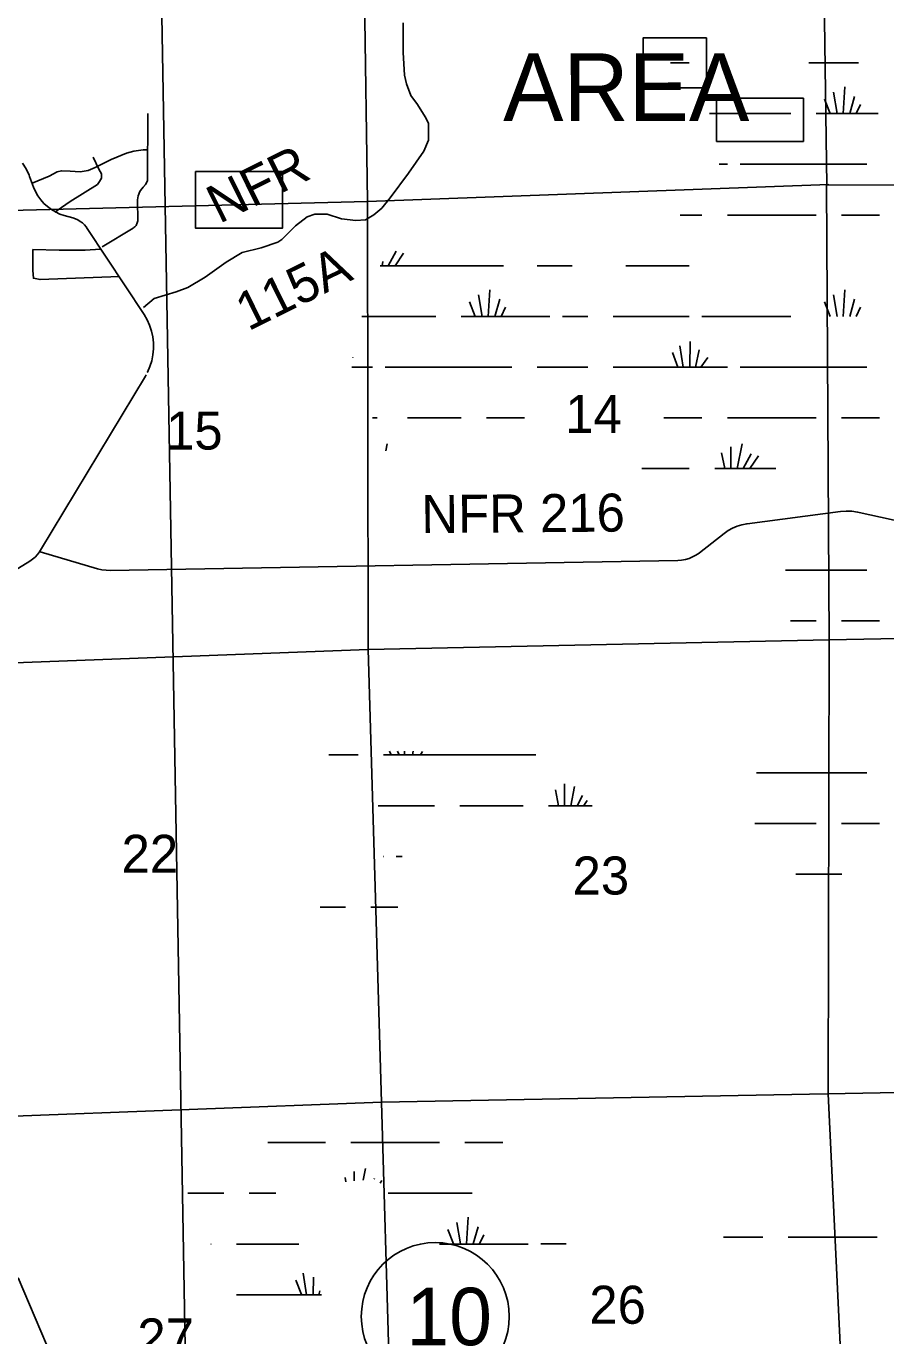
# Model space of a CAD drawing. Extents: x 2480962 to 2688785, y 277103 to 599240.
# Drawn here: x 2598432 to 2608603, y 442588 to 458082 of the extents above; entities that cross this region are included whole.
import ezdxf

# ---------------------------------------------------------------- set-up
doc = ezdxf.new("R2010")
doc.units = 0
for name, color, linetype in [('Divided_Highway', 7, 'Continuous'), ('Level 31', 7, 'Continuous'), ('Level 44', 7, 'Continuous'), ('Local Roads Improved', 7, 'Continuous'), ('Local Roads Related Text', 7, 'Continuous'), ('Planning Number US Highways', 7, 'Continuous'), ('Section Lines', 7, 'Continuous'), ('Section Numbers', 7, 'Continuous'), ('Swamps', 7, 'Continuous')]:
    doc.layers.add(name, color=color, linetype=linetype)

msp = doc.modelspace()

# ---------------------------------------------------------------- linework, layer by layer
at = {"layer": 'Divided_Highway'}
msp.add_line((2600799.421, 414762.355), (2600001.432, 460214.017), dxfattribs=at)
at = {"layer": 'Level 31'}
for points in [[(2606481.942, 457943.709), (2605731.294, 457943.709), (2605731.294, 457350.694), (2606481.942, 457350.694)], [(2607627.668, 457232.091), (2606600.465, 457232.091), (2606600.465, 456718.144), (2607627.668, 456718.144)], [(2601464.45, 456362.335), (2600437.247, 456362.335), (2600437.247, 455690.25), (2601464.45, 455690.25)]]:
    msp.add_lwpolyline(points, close=True, dxfattribs=at)
at = {"layer": 'Local Roads Improved'}
for p, q in [((2599873.012, 457047.638), (2599868.465, 456285.277)), ((2598471.682, 456302.805), (2598518.787, 456177.402)), ((2599830.334, 456192.694), (2599814.374, 456176.413)), ((2599749.023, 456013.245), (2599752.022, 455791.542)), ((2598880.665, 455843.218), (2598985.492, 455813.1)), ((2599154.919, 455688.573), (2599827.03, 454669.258)), ((2599697.771, 455693.41), (2599332.347, 455470.758)), ((2598602.645, 451882.083), (2599842.081, 453942.71)), ((2606964.152, 452195.687), (2608066.39, 452338.855)), ((2608289.097, 452329.141), (2611255.027, 451677.276)), ((2606399.373, 451853.027), (2606689.888, 452080.714)), ((2598599.058, 451861.375), (2599274.31, 451663.367)), ((2597005.743, 450854.193), (2598474.557, 451753.012)), ((2599425.601, 451643.007), (2606142.68, 451761.873)), ((2598672.824, 442484.922), (2598337.502, 443272.871))]:
    msp.add_line(p, q, dxfattribs=at)
for points in [[(2599818.162, 454754.215), (2599947.956, 454859.672), (2600207.544, 454940.794), (2600345.45, 454989.466), (2600548.254, 455111.148), (2600799.73, 455289.615), (2600986.309, 455403.185), (2601213.449, 455459.97), (2601408.14, 455524.867), (2601456.813, 455557.316), (2601619.056, 455719.559), (2601756.962, 455825.016), (2601846.195, 455857.465), (2601992.214, 455857.465), (2602162.569, 455800.68), (2602332.924, 455784.456), (2602446.493, 455792.568), (2602543.839, 455849.353), (2602641.185, 455930.474), (2602738.53, 456052.156), (2602957.558, 456344.193), (2603136.025, 456603.781), (2603192.81, 456733.576), (2603192.81, 456855.258), (2603192.81, 456936.379), (2603152.249, 457009.388), (2603063.016, 457155.407), (2602981.894, 457260.864), (2602933.222, 457398.771), (2602908.885, 457504.228), (2602892.661, 457771.929), (2602892.661, 458031.517), (2602892.661, 458120.751)], [(2598501.56, 456223.333), (2598704.41, 456308.31), (2598800.352, 456357.652), (2598849.694, 456371.358), (2598951.119, 456365.876), (2599071.733, 456360.394), (2599164.934, 456374.1), (2599249.912, 456409.735), (2599436.315, 456502.937), (2599619.976, 456579.691), (2599704.954, 456604.362), (2599814.603, 456618.068), (2599861.203, 456620.809), (2599861.203, 456620.809)], [(2598389.53, 456462.342), (2598431.13, 456392.844), (2598465.238, 456319.379), (2598471.682, 456302.805)], [(2599225.241, 456533.09), (2599291.03, 456390.547), (2599321.184, 456335.723), (2599321.184, 456283.639), (2599299.254, 456245.262), (2599274.583, 456209.627), (2598953.861, 456006.776), (2598800.352, 455902.61), (2598775.681, 455883.422)], [(2598518.787, 456177.402), (2598541.752, 456124.804), (2598570.09, 456074.896), (2598603.489, 456028.222), (2598641.585, 455985.295), (2598683.958, 455946.586), (2598730.146, 455912.517), (2598779.642, 455883.464), (2598831.904, 455859.744), (2598880.665, 455843.218)], [(2599814.374, 456176.413), (2599798.536, 456158.466), (2599784.662, 456138.964), (2599772.901, 456118.117), (2599763.384, 456096.155), (2599756.215, 456073.319), (2599751.472, 456049.859), (2599749.207, 456026.031), (2599749.023, 456013.245)], [(2599868.465, 456285.277), (2599867.651, 456271.338), (2599865.386, 456257.561), (2599861.691, 456244.096), (2599856.61, 456231.091), (2599850.197, 456218.688), (2599842.523, 456207.024), (2599833.672, 456196.226), (2599830.334, 456192.694)], [(2598985.492, 455813.1), (2599015.499, 455802.75), (2599044.26, 455789.319), (2599071.459, 455772.956), (2599096.799, 455753.84), (2599120.003, 455732.179), (2599140.815, 455708.212), (2599154.919, 455688.573)], [(2599752.022, 455791.542), (2599751.563, 455779.71), (2599749.869, 455767.991), (2599746.959, 455756.514), (2599742.866, 455745.404), (2599737.633, 455734.782), (2599731.319, 455724.764), (2599723.994, 455715.463), (2599715.735, 455706.978), (2599706.635, 455699.403), (2599697.771, 455693.41)], [(2599534.77, 455120.164), (2598595.903, 455083.652), (2598517.664, 455099.3), (2598512.448, 455193.187), (2598512.448, 455412.256), (2598512.448, 455438.336), (2598820.188, 455433.12), (2599127.928, 455433.12), (2599310.485, 455443.551)], [(2599827.03, 454669.258), (2599863.133, 454607.721), (2599892.607, 454542.747), (2599915.127, 454475.048), (2599930.447, 454405.366), (2599938.4, 454334.465), (2599938.898, 454263.119), (2599931.936, 454192.114), (2599917.59, 454122.224), (2599896.017, 454054.217), (2599867.454, 453988.838), (2599864.371, 453982.758)], [(2599842.081, 453942.71), (2599850.713, 453957.478)], [(2608066.39, 452338.855), (2608134.06, 452344.063), (2608201.904, 452342.169), (2608269.179, 452333.193), (2608289.097, 452329.141)], [(2606689.888, 452080.714), (2606738.021, 452114.526), (2606789.423, 452143.12), (2606843.534, 452166.186), (2606899.759, 452183.469), (2606957.483, 452194.78), (2606964.152, 452195.687)], [(2598474.557, 451753.012), (2598507.557, 451775.662), (2598538.008, 451801.637), (2598565.579, 451830.653), (2598589.964, 451862.392), (2598602.645, 451882.083)], [(2606142.68, 451761.873), (2606187.414, 451765.013), (2606231.574, 451772.81), (2606274.677, 451785.181), (2606316.251, 451801.99), (2606355.841, 451823.052), (2606393.012, 451848.137), (2606399.373, 451853.027)], [(2599274.31, 451663.367), (2599325.829, 451651.147), (2599378.344, 451644.38), (2599425.601, 451643.007)]]:
    msp.add_lwpolyline(points, dxfattribs=at)
at = {"layer": 'Planning Number US Highways'}
msp.add_circle((2603272.369, 442816.14), 875, dxfattribs=at)
at = {"layer": 'Section Lines'}
for p, q in [((2607834.885, 461478.013), (2607905.041, 456199.96)), ((2602470.87, 456008.717), (2602392.032, 461297.775)), ((2602470.87, 456008.768), (2607929.608, 456207.264)), ((2607903.429, 456206.309), (2613360.162, 456178.288)), ((2607903.429, 456206.309), (2607931.911, 450819.864)), ((2597223.549, 455875.68), (2602470.87, 456008.717)), ((2602478.304, 450708.223), (2602470.87, 456008.768)), ((2607931.911, 450819.864), (2613319.455, 450926.862)), ((2602478.304, 450708.223), (2607931.911, 450819.864)), ((2607931.911, 450819.864), (2607919.944, 445449.014)), ((2602478.306, 450708.223), (2597332.488, 450513.138)), ((2602636.608, 445353.54), (2602478.306, 450708.223)), ((2607912.122, 445448.861), (2613411.446, 445556.59)), ((2597403.462, 445151.69), (2602636.608, 445353.54)), ((2602636.608, 445353.54), (2607912.122, 445448.861)), ((2602790.466, 440010.561), (2602636.608, 445353.54)), ((2607919.944, 445449.014), (2608176.107, 440121.819))]:
    msp.add_line(p, q, dxfattribs=at)
at = {"layer": 'Swamps'}
for p, q in [((2607692.038, 457647.508), (2608278.299, 457647.516)), ((2608028.816, 457047.591), (2607982.56, 457301.974)), ((2608099.816, 457047.542), (2608117.051, 457363.618)), ((2608176.502, 457047.721), (2608234.734, 457251.542)), ((2607943.742, 457047.678), (2607878.268, 457219.545)), ((2608253.098, 457047.644), (2608301.982, 457156.277)), ((2607778.306, 457047.505), (2608511.996, 457047.515)), ((2606878.314, 456447.488), (2608378.316, 456447.509)), ((2606728.322, 455847.482), (2607778.324, 455847.497)), ((2608078.324, 455847.501), (2608528.325, 455847.507)), ((2602895.489, 455397.247), (2602796.17, 455248.265)), ((2604478.327, 455247.447), (2604890.594, 455247.453)), ((2605528.328, 455247.462), (2605978.329, 455247.468)), ((2605978.329, 455247.468), (2606278.33, 455247.472)), ((2603899.843, 454647.467), (2603917.079, 454963.543)), ((2608099.851, 454647.525), (2608117.086, 454963.602)), ((2603743.769, 454647.604), (2603678.295, 454819.47)), ((2603828.843, 454647.516), (2603782.587, 454901.899)), ((2603976.529, 454647.646), (2604034.761, 454851.467)), ((2604053.125, 454647.569), (2604102.009, 454756.203)), ((2607943.776, 454647.662), (2607878.303, 454819.528)), ((2608028.851, 454647.574), (2607982.595, 454901.957)), ((2608176.537, 454647.704), (2608234.769, 454851.526)), ((2608253.133, 454647.627), (2608302.017, 454756.261)), ((2603578.333, 454647.431), (2604628.335, 454647.445)), ((2604778.336, 454647.447), (2605078.336, 454647.451)), ((2605378.337, 454647.456), (2605978.338, 454647.464)), ((2605978.338, 454647.464), (2606278.338, 454647.468)), ((2606428.339, 454647.47), (2607478.341, 454647.485)), ((2606206.349, 454047.527), (2606166.954, 454300.763)), ((2606284.511, 454047.483), (2606290.238, 454351.199)), ((2606144.027, 454048.449), (2606077.955, 454221.244)), ((2606351.61, 454047.275), (2606394.494, 454253.128)), ((2606413.806, 454046.968), (2606497.584, 454160.67)), ((2602678.34, 454047.414), (2604178.343, 454047.435)), ((2604478.343, 454047.439), (2605078.345, 454047.448)), ((2605378.345, 454047.452), (2605978.346, 454047.46)), ((2605978.346, 454047.46), (2606728.348, 454047.47)), ((2606878.348, 454047.472), (2608378.351, 454047.493)), ((2602528.348, 453447.409), (2602586.57, 453447.409)), ((2602944.57, 453447.414), (2603578.35, 453447.423)), ((2603878.351, 453447.427), (2604328.352, 453447.433)), ((2605978.355, 453447.456), (2606428.356, 453447.462)), ((2606728.356, 453447.466), (2607778.358, 453447.481)), ((2608078.359, 453447.485), (2608528.36, 453447.491)), ((2606769.307, 453106.027), (2606769.311, 452847.463)), ((2606902.212, 453142.275), (2606843.275, 452847.569)), ((2606660.567, 453033.531), (2606697.779, 452847.484)), ((2607010.954, 453021.453), (2606916.948, 452846.865)), ((2607095.531, 452997.289), (2606996.213, 452848.308)), ((2605978.363, 452847.452), (2606278.364, 452847.456)), ((2608078.394, 451047.469), (2608528.395, 451047.475)), ((2602661.312, 449459.403), (2604011.315, 449459.421)), ((2604011.315, 449459.421), (2604461.316, 449459.427)), ((2604693.528, 449045.495), (2604730.739, 448859.448)), ((2604802.268, 449117.991), (2604802.271, 448859.427)), ((2603561.322, 448859.411), (2604011.323, 448859.417)), ((2604011.323, 448859.417), (2604311.324, 448859.421)), ((2608078.429, 448647.452), (2608528.43, 448647.458)), ((2601522.055, 444873.86), (2601972.057, 444873.866)), ((2602272.057, 444873.87), (2603322.06, 444873.884)), ((2603622.061, 444873.887), (2604072.063, 444873.893)), ((2603572.587, 443673.961), (2603526.331, 443928.344)), ((2603643.587, 443673.912), (2603660.823, 443989.988)), ((2603487.513, 443674.049), (2603422.039, 443845.915)), ((2603720.273, 443674.091), (2603778.506, 443877.912)), ((2603796.87, 443674.014), (2603845.753, 443782.647)), ((2606699.255, 443753.75), (2607149.257, 443753.755)), ((2607449.257, 443753.759), (2608499.261, 443753.773)), ((2600922.07, 443673.845), (2601522.072, 443673.853)), ((2603322.077, 443673.876), (2604372.08, 443673.889)), ((2604522.081, 443673.891), (2604822.082, 443673.895)), ((2601750.083, 443073.916), (2601710.688, 443327.152)), ((2601687.761, 443074.838), (2601621.689, 443247.634)), ((2600922.078, 443073.842), (2601522.08, 443073.849))]:
    msp.add_line(p, q, dxfattribs=at)
for points in [[(2606053.774, 457647.485), (2606278.295, 457647.488)], [(2606518.993, 457047.487), (2607478.306, 457047.501)], [(2606631.126, 456447.485), (2606728.313, 456447.486)], [(2606169.231, 455847.474), (2606428.321, 455847.478)], [(2602810.912, 455421.411), (2602716.906, 455246.822)], [(2602620.242, 455247.421), (2604078.326, 455247.441)], [(2602653.348, 455298.097), (2602643.233, 455247.526)], [(2602404.029, 454647.414), (2603278.333, 454647.426)], [(2602295.819, 454158.226), (2602297.576, 454160.612)], [(2602285.893, 454047.409), (2602528.34, 454047.412)], [(2602702.204, 453142.217), (2602685.59, 453059.141)], [(2605714.848, 452847.448), (2605978.363, 452847.452)], [(2606578.365, 452847.46), (2607302.306, 452847.47)], [(2607416.265, 451647.464), (2608378.386, 451647.477)], [(2607477.067, 451047.46), (2607778.393, 451047.465)], [(2602731.95, 449504.58), (2602751.219, 449459.404)], [(2602826.365, 449503.954), (2602843.837, 449459.405)], [(2602909.971, 449503.401), (2602909.971, 449459.406)], [(2603012.2, 449502.725), (2603001.347, 449459.306)], [(2603122.908, 449501.992), (2603098.144, 449459.537)], [(2602014.698, 449459.394), (2602361.311, 449459.399)], [(2607071.578, 449247.443), (2608378.421, 449247.46)], [(2604921.475, 449085.748), (2604876.236, 448859.533)], [(2605016.112, 448981.784), (2604949.909, 448858.829)], [(2605070.412, 448922.132), (2605029.173, 448860.272)], [(2602596.011, 448859.398), (2603261.322, 448859.407)], [(2604611.325, 448859.425), (2605127.488, 448859.432)], [(2607055.3, 448647.439), (2607778.428, 448647.448)], [(2602655.821, 448259.395), (2602661.329, 448259.395)], [(2602811.329, 448259.397), (2602879.723, 448259.398)], [(2607538.376, 448047.441), (2608084.759, 448047.448)], [(2601908.674, 447659.381), (2602211.336, 447659.385)], [(2602511.336, 447659.389), (2602830.74, 447659.394)], [(2601292.57, 444873.857), (2601522.055, 444873.86)], [(2602313.008, 444532.43), (2602313.01, 444419.883)], [(2602445.913, 444568.678), (2602417.966, 444428.929)], [(2602204.268, 444459.935), (2602213.987, 444411.348)], [(2602554.655, 444447.857), (2602550.62, 444440.362)], [(2602639.232, 444423.693), (2602619.39, 444393.929)], [(2600344.182, 444273.842), (2600772.061, 444273.847)], [(2601072.062, 444273.851), (2601387.638, 444273.855)], [(2602716.473, 444273.872), (2603707.157, 444273.885)], [(2606682.706, 443753.749), (2606699.255, 443753.75)], [(2600615.725, 443673.841), (2600622.069, 443673.842)], [(2601522.072, 443673.853), (2601656.175, 443673.855)], [(2601828.245, 443073.872), (2601832.145, 443280.682)], [(2601522.08, 443073.849), (2601924.713, 443073.854)], [(2601895.344, 443073.664), (2601904.7, 443118.57)]]:
    msp.add_lwpolyline(points, dxfattribs=at)

# ---------------------------------------------------------------- texts
at = {"layer": 'Level 44'}
msp.add_text('AREA', height=800, rotation=0.0287389, dxfattribs=at).set_placement((2604075.389, 456959.806))
at = {"layer": 'Local Roads Related Text'}
for s, rotation, p in [('NFR', 26.2751083, (2600716.497, 455740.46)), ('115A', 26.2751, (2601059.191, 454469.727)), ('NFR 216', 0.4431833, (2603109.148, 452084.295))]:
    msp.add_text(s, height=450, rotation=rotation, dxfattribs=at).set_placement(p)
at = {"layer": 'Planning Number US Highways'}
msp.add_text('10', height=680, dxfattribs=at).set_placement((2602931.115, 442476.141))
at = {"layer": 'Section Numbers'}
for s, rotation, p in [('14', 359.9792861, (2604810.695, 453270.072)), ('15', 359.9792972, (2600086.725, 453072.886)), ('22', 359.9794833, (2599560.291, 448065.553)), ('23', 359.9792528, (2604897.232, 447808.625)), ('26', 359.9792222, (2605095.055, 442730.436)), ('27', 359.9795222, (2599747.531, 442343.032))]:
    msp.add_text(s, height=450, rotation=rotation, dxfattribs=at).set_placement(p)

doc.saveas('drawing.dxf')
